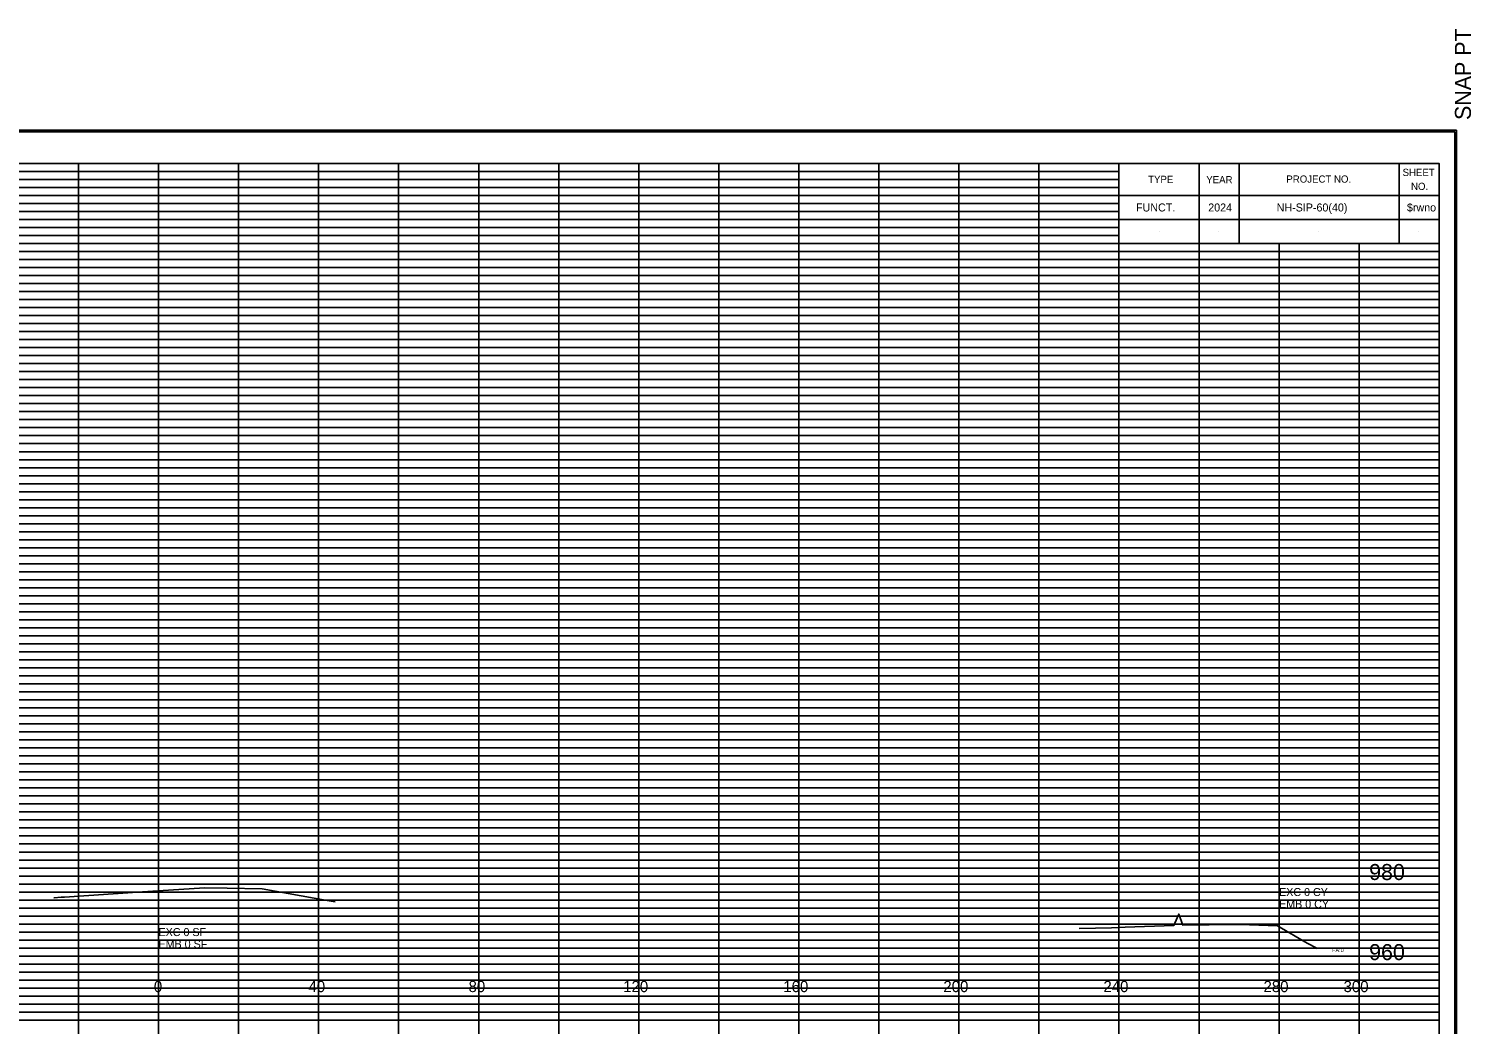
# Model space of a CAD drawing. Extents: x 2313580 to 2322968, y 282099 to 303247.
# Drawn here: x 2321124.9 to 2321485.3, y 287792.7 to 288041.3 of the extents above; entities that cross this region are included whole.
import ezdxf

# ---------------------------------------------------------------- set-up
doc = ezdxf.new("R2010")
doc.units = 0
for name, color, linetype in [('DESIGN - EARTHWORK - Excavation Limit Lines', 7, 'Continuous'), ('DESIGN - SCRATCH - User 1', 7, 'Continuous'), ('DESIGN - SHEET - Corner Text', 7, 'Continuous'), ('DESIGN - SHEET - Light Grid', 7, 'Continuous'), ('DESIGN - SHEET - Linework', 7, 'Continuous'), ('DESIGN - SHEET - Plot Shape', 7, 'Continuous'), ('DESIGN - TYPICAL - Text', 7, 'Continuous'), ('Prop_ CL text', 7, 'Continuous'), ('SURVEY - GROUND - Top of Ground', 7, 'Continuous')]:
    doc.layers.add(name, color=color, linetype=linetype)

msp = doc.modelspace()

# ---------------------------------------------------------------- linework, layer by layer
at = {"layer": 'DESIGN - SCRATCH - User 1'}
for p, q in [((2321407.28, 287996.67), (2321407.28, 287996.67)), ((2321422.08, 287996.67), (2321422.08, 287996.67)), ((2321447.08, 287996.67), (2321447.08, 287996.67)), ((2321472.08, 287996.67), (2321472.08, 287996.67)), ((2321407.28, 287990.67), (2321407.28, 287990.67)), ((2321422.08, 287990.67), (2321422.08, 287990.67)), ((2321447.08, 287990.67), (2321447.08, 287990.67)), ((2321472.08, 287990.67), (2321472.08, 287990.67))]:
    msp.add_line(p, q, dxfattribs=at)
at = {"layer": 'DESIGN - SHEET - Light Grid'}
for p, q in [((2320997.28, 288005.67), (2321157.28, 288005.67)), ((2320997.28, 288003.67), (2321157.28, 288003.67)), ((2321157.28, 288005.67), (2321317.28, 288005.67)), ((2321157.28, 288003.67), (2321317.28, 288003.67)), ((2321317.28, 288005.67), (2321397.28, 288005.67)), ((2321317.28, 288003.67), (2321397.28, 288003.67)), ((2320997.28, 288001.67), (2321157.28, 288001.67)), ((2320997.28, 287999.67), (2321157.28, 287999.67)), ((2321157.28, 288001.67), (2321317.28, 288001.67)), ((2321157.28, 287999.67), (2321317.28, 287999.67)), ((2321317.28, 288001.67), (2321397.28, 288001.67)), ((2321317.28, 287999.67), (2321397.28, 287999.67)), ((2320997.28, 287997.67), (2321157.28, 287997.67)), ((2320997.28, 287995.67), (2321157.28, 287995.67)), ((2321157.28, 287997.67), (2321317.28, 287997.67)), ((2321157.28, 287995.67), (2321317.28, 287995.67)), ((2321317.28, 287997.67), (2321397.28, 287997.67)), ((2321317.28, 287995.67), (2321397.28, 287995.67)), ((2320997.28, 287993.67), (2321157.28, 287993.67)), ((2320997.28, 287991.67), (2321157.28, 287991.67)), ((2321157.28, 287993.67), (2321317.28, 287993.67)), ((2321157.28, 287991.67), (2321317.28, 287991.67)), ((2321317.28, 287993.67), (2321397.28, 287993.67)), ((2321317.28, 287991.67), (2321397.28, 287991.67)), ((2320997.28, 287989.67), (2321157.28, 287989.67)), ((2321157.28, 287989.67), (2321317.28, 287989.67)), ((2321317.28, 287989.67), (2321397.28, 287989.67)), ((2320997.28, 287985.67), (2321157.28, 287985.67)), ((2321157.28, 287985.67), (2321317.28, 287985.67)), ((2321317.28, 287985.67), (2321477.28, 287985.67)), ((2320997.28, 287983.67), (2321157.28, 287983.67)), ((2320997.28, 287981.67), (2321157.28, 287981.67)), ((2321157.28, 287983.67), (2321317.28, 287983.67)), ((2321157.28, 287981.67), (2321317.28, 287981.67)), ((2321317.28, 287983.67), (2321477.28, 287983.67)), ((2321317.28, 287981.67), (2321477.28, 287981.67)), ((2320997.28, 287979.67), (2321157.28, 287979.67)), ((2320997.28, 287977.67), (2321157.28, 287977.67)), ((2321157.28, 287979.67), (2321317.28, 287979.67)), ((2321157.28, 287977.67), (2321317.28, 287977.67)), ((2321317.28, 287979.67), (2321477.28, 287979.67)), ((2321317.28, 287977.67), (2321477.28, 287977.67)), ((2320997.28, 287975.67), (2321157.28, 287975.67)), ((2320997.28, 287973.67), (2321157.28, 287973.67)), ((2321157.28, 287975.67), (2321317.28, 287975.67)), ((2321157.28, 287973.67), (2321317.28, 287973.67)), ((2321317.28, 287975.67), (2321477.28, 287975.67)), ((2321317.28, 287973.67), (2321477.28, 287973.67)), ((2320997.28, 287971.67), (2321157.28, 287971.67)), ((2321157.28, 287971.67), (2321317.28, 287971.67)), ((2321317.28, 287971.67), (2321477.28, 287971.67)), ((2320997.28, 287969.67), (2321157.28, 287969.67)), ((2321157.28, 287969.67), (2321317.28, 287969.67)), ((2321317.28, 287969.67), (2321477.28, 287969.67)), ((2320997.28, 287965.67), (2321157.28, 287965.67)), ((2320997.28, 287963.67), (2321157.28, 287963.67)), ((2321157.28, 287965.67), (2321317.28, 287965.67)), ((2321157.28, 287963.67), (2321317.28, 287963.67)), ((2321317.28, 287965.67), (2321477.28, 287965.67)), ((2321317.28, 287963.67), (2321477.28, 287963.67)), ((2320997.28, 287961.67), (2321157.28, 287961.67)), ((2320997.28, 287959.67), (2321157.28, 287959.67)), ((2321157.28, 287961.67), (2321317.28, 287961.67)), ((2321157.28, 287959.67), (2321317.28, 287959.67)), ((2321317.28, 287961.67), (2321477.28, 287961.67)), ((2321317.28, 287959.67), (2321477.28, 287959.67)), ((2320997.28, 287957.67), (2321157.28, 287957.67)), ((2320997.28, 287955.67), (2321157.28, 287955.67)), ((2321157.28, 287957.67), (2321317.28, 287957.67)), ((2321157.28, 287955.67), (2321317.28, 287955.67)), ((2321317.28, 287957.67), (2321477.28, 287957.67)), ((2321317.28, 287955.67), (2321477.28, 287955.67)), ((2320997.28, 287953.67), (2321157.28, 287953.67)), ((2321157.28, 287953.67), (2321317.28, 287953.67)), ((2321317.28, 287953.67), (2321477.28, 287953.67)), ((2320997.28, 287951.67), (2321157.28, 287951.67)), ((2320997.28, 287949.67), (2321157.28, 287949.67)), ((2321157.28, 287951.67), (2321317.28, 287951.67)), ((2321157.28, 287949.67), (2321317.28, 287949.67)), ((2321317.28, 287951.67), (2321477.28, 287951.67)), ((2321317.28, 287949.67), (2321477.28, 287949.67)), ((2320997.28, 287945.67), (2321157.28, 287945.67)), ((2321157.28, 287945.67), (2321317.28, 287945.67)), ((2321317.28, 287945.67), (2321477.28, 287945.67)), ((2320997.28, 287943.67), (2321157.28, 287943.67)), ((2320997.28, 287941.67), (2321157.28, 287941.67)), ((2321157.28, 287943.67), (2321317.28, 287943.67)), ((2321157.28, 287941.67), (2321317.28, 287941.67)), ((2321317.28, 287943.67), (2321477.28, 287943.67)), ((2321317.28, 287941.67), (2321477.28, 287941.67)), ((2320997.28, 287939.67), (2321157.28, 287939.67)), ((2320997.28, 287937.67), (2321157.28, 287937.67)), ((2321157.28, 287939.67), (2321317.28, 287939.67)), ((2321157.28, 287937.67), (2321317.28, 287937.67)), ((2321317.28, 287939.67), (2321477.28, 287939.67)), ((2321317.28, 287937.67), (2321477.28, 287937.67)), ((2320997.28, 287935.67), (2321157.28, 287935.67)), ((2321157.28, 287935.67), (2321317.28, 287935.67)), ((2321317.28, 287935.67), (2321477.28, 287935.67)), ((2320997.28, 287933.67), (2321157.28, 287933.67)), ((2320997.28, 287931.67), (2321157.28, 287931.67)), ((2321157.28, 287933.67), (2321317.28, 287933.67)), ((2321157.28, 287931.67), (2321317.28, 287931.67)), ((2321317.28, 287933.67), (2321477.28, 287933.67)), ((2321317.28, 287931.67), (2321477.28, 287931.67)), ((2320997.28, 287929.67), (2321157.28, 287929.67)), ((2321157.28, 287929.67), (2321317.28, 287929.67)), ((2321317.28, 287929.67), (2321477.28, 287929.67)), ((2320997.28, 287925.67), (2321157.28, 287925.67)), ((2320997.28, 287923.67), (2321157.28, 287923.67)), ((2321157.28, 287925.67), (2321317.28, 287925.67)), ((2321157.28, 287923.67), (2321317.28, 287923.67)), ((2321317.28, 287925.67), (2321477.28, 287925.67)), ((2321317.28, 287923.67), (2321477.28, 287923.67)), ((2320997.28, 287921.67), (2321157.28, 287921.67)), ((2320997.28, 287919.67), (2321157.28, 287919.67)), ((2321157.28, 287921.67), (2321317.28, 287921.67)), ((2321157.28, 287919.67), (2321317.28, 287919.67)), ((2321317.28, 287921.67), (2321477.28, 287921.67)), ((2321317.28, 287919.67), (2321477.28, 287919.67)), ((2320997.28, 287917.67), (2321157.28, 287917.67)), ((2321157.28, 287917.67), (2321317.28, 287917.67)), ((2321317.28, 287917.67), (2321477.28, 287917.67)), ((2320997.28, 287915.67), (2321157.28, 287915.67)), ((2320997.28, 287913.67), (2321157.28, 287913.67)), ((2321157.28, 287915.67), (2321317.28, 287915.67)), ((2321157.28, 287913.67), (2321317.28, 287913.67)), ((2321317.28, 287915.67), (2321477.28, 287915.67)), ((2321317.28, 287913.67), (2321477.28, 287913.67)), ((2320997.28, 287911.67), (2321157.28, 287911.67)), ((2320997.28, 287909.67), (2321157.28, 287909.67)), ((2321157.28, 287911.67), (2321317.28, 287911.67)), ((2321157.28, 287909.67), (2321317.28, 287909.67)), ((2321317.28, 287911.67), (2321477.28, 287911.67)), ((2321317.28, 287909.67), (2321477.28, 287909.67)), ((2320997.28, 287905.67), (2321157.28, 287905.67)), ((2321157.28, 287905.67), (2321317.28, 287905.67)), ((2321317.28, 287905.67), (2321477.28, 287905.67)), ((2320997.28, 287903.67), (2321157.28, 287903.67)), ((2320997.28, 287901.67), (2321157.28, 287901.67)), ((2321157.28, 287903.67), (2321317.28, 287903.67)), ((2321157.28, 287901.67), (2321317.28, 287901.67)), ((2321317.28, 287903.67), (2321477.28, 287903.67)), ((2321317.28, 287901.67), (2321477.28, 287901.67)), ((2320997.28, 287899.67), (2321157.28, 287899.67)), ((2321157.28, 287899.67), (2321317.28, 287899.67)), ((2321317.28, 287899.67), (2321477.28, 287899.67)), ((2320997.28, 287897.67), (2321157.28, 287897.67)), ((2320997.28, 287895.67), (2321157.28, 287895.67)), ((2321157.28, 287897.67), (2321317.28, 287897.67)), ((2321157.28, 287895.67), (2321317.28, 287895.67)), ((2321317.28, 287897.67), (2321477.28, 287897.67)), ((2321317.28, 287895.67), (2321477.28, 287895.67)), ((2320997.28, 287893.67), (2321157.28, 287893.67)), ((2320997.28, 287891.67), (2321157.28, 287891.67)), ((2321157.28, 287893.67), (2321317.28, 287893.67)), ((2321157.28, 287891.67), (2321317.28, 287891.67)), ((2321317.28, 287893.67), (2321477.28, 287893.67)), ((2321317.28, 287891.67), (2321477.28, 287891.67)), ((2320997.28, 287889.67), (2321157.28, 287889.67)), ((2321157.28, 287889.67), (2321317.28, 287889.67)), ((2321317.28, 287889.67), (2321477.28, 287889.67)), ((2320997.28, 287885.67), (2321157.28, 287885.67)), ((2320997.28, 287883.67), (2321157.28, 287883.67)), ((2321157.28, 287885.67), (2321317.28, 287885.67)), ((2321157.28, 287883.67), (2321317.28, 287883.67)), ((2321317.28, 287885.67), (2321477.28, 287885.67)), ((2321317.28, 287883.67), (2321477.28, 287883.67)), ((2320997.28, 287881.67), (2321157.28, 287881.67)), ((2321157.28, 287881.67), (2321317.28, 287881.67)), ((2321317.28, 287881.67), (2321477.28, 287881.67)), ((2320997.28, 287879.67), (2321157.28, 287879.67)), ((2320997.28, 287877.67), (2321157.28, 287877.67)), ((2321157.28, 287879.67), (2321317.28, 287879.67)), ((2321157.28, 287877.67), (2321317.28, 287877.67)), ((2321317.28, 287879.67), (2321477.28, 287879.67)), ((2321317.28, 287877.67), (2321477.28, 287877.67)), ((2320997.28, 287875.67), (2321157.28, 287875.67)), ((2320997.28, 287873.67), (2321157.28, 287873.67)), ((2321157.28, 287875.67), (2321317.28, 287875.67)), ((2321157.28, 287873.67), (2321317.28, 287873.67)), ((2321317.28, 287875.67), (2321477.28, 287875.67)), ((2321317.28, 287873.67), (2321477.28, 287873.67)), ((2320997.28, 287871.67), (2321157.28, 287871.67)), ((2320997.28, 287869.67), (2321157.28, 287869.67)), ((2321157.28, 287871.67), (2321317.28, 287871.67)), ((2321157.28, 287869.67), (2321317.28, 287869.67)), ((2321317.28, 287871.67), (2321477.28, 287871.67)), ((2321317.28, 287869.67), (2321477.28, 287869.67)), ((2320997.28, 287865.67), (2321157.28, 287865.67)), ((2321157.28, 287865.67), (2321317.28, 287865.67)), ((2321317.28, 287865.67), (2321477.28, 287865.67)), ((2320997.28, 287863.67), (2321157.28, 287863.67)), ((2321157.28, 287863.67), (2321317.28, 287863.67)), ((2321317.28, 287863.67), (2321477.28, 287863.67)), ((2320997.28, 287861.67), (2321157.28, 287861.67)), ((2320997.28, 287859.67), (2321157.28, 287859.67)), ((2321157.28, 287861.67), (2321317.28, 287861.67)), ((2321157.28, 287859.67), (2321317.28, 287859.67)), ((2321317.28, 287861.67), (2321477.28, 287861.67)), ((2321317.28, 287859.67), (2321477.28, 287859.67)), ((2320997.28, 287857.67), (2321157.28, 287857.67)), ((2320997.28, 287855.67), (2321157.28, 287855.67)), ((2321157.28, 287857.67), (2321317.28, 287857.67)), ((2321157.28, 287855.67), (2321317.28, 287855.67)), ((2321317.28, 287857.67), (2321477.28, 287857.67)), ((2321317.28, 287855.67), (2321477.28, 287855.67)), ((2320997.28, 287853.67), (2321157.28, 287853.67)), ((2320997.28, 287851.67), (2321157.28, 287851.67)), ((2321157.28, 287853.67), (2321317.28, 287853.67)), ((2321157.28, 287851.67), (2321317.28, 287851.67)), ((2321317.28, 287853.67), (2321477.28, 287853.67)), ((2321317.28, 287851.67), (2321477.28, 287851.67)), ((2320997.28, 287849.67), (2321157.28, 287849.67)), ((2321157.28, 287849.67), (2321317.28, 287849.67)), ((2321317.28, 287849.67), (2321477.28, 287849.67)), ((2320997.28, 287845.67), (2321157.28, 287845.67)), ((2321157.28, 287845.67), (2321317.28, 287845.67)), ((2321317.28, 287845.67), (2321477.28, 287845.67)), ((2320997.28, 287843.67), (2321157.28, 287843.67)), ((2320997.28, 287841.67), (2321157.28, 287841.67)), ((2321157.28, 287843.67), (2321317.28, 287843.67)), ((2321157.28, 287841.67), (2321317.28, 287841.67)), ((2321317.28, 287843.67), (2321477.28, 287843.67)), ((2321317.28, 287841.67), (2321477.28, 287841.67)), ((2320997.28, 287839.67), (2321157.28, 287839.67)), ((2320997.28, 287837.67), (2321157.28, 287837.67)), ((2321157.28, 287839.67), (2321317.28, 287839.67)), ((2321157.28, 287837.67), (2321317.28, 287837.67)), ((2321317.28, 287839.67), (2321477.28, 287839.67)), ((2321317.28, 287837.67), (2321477.28, 287837.67)), ((2320997.28, 287835.67), (2321157.28, 287835.67)), ((2320997.28, 287833.67), (2321157.28, 287833.67)), ((2321157.28, 287835.67), (2321317.28, 287835.67)), ((2321157.28, 287833.67), (2321317.28, 287833.67)), ((2321317.28, 287835.67), (2321477.28, 287835.67)), ((2321317.28, 287833.67), (2321477.28, 287833.67)), ((2320997.28, 287831.67), (2321157.28, 287831.67)), ((2320997.28, 287829.67), (2321157.28, 287829.67)), ((2321157.28, 287831.67), (2321317.28, 287831.67)), ((2321157.28, 287829.67), (2321317.28, 287829.67)), ((2321317.28, 287831.67), (2321477.28, 287831.67)), ((2321317.28, 287829.67), (2321477.28, 287829.67)), ((2320997.28, 287825.67), (2321157.28, 287825.67)), ((2320997.28, 287823.67), (2321157.28, 287823.67)), ((2321157.28, 287825.67), (2321317.28, 287825.67)), ((2321157.28, 287823.67), (2321317.28, 287823.67)), ((2321317.28, 287825.67), (2321477.28, 287825.67)), ((2321317.28, 287823.67), (2321477.28, 287823.67)), ((2320997.28, 287821.67), (2321157.28, 287821.67)), ((2320997.28, 287819.67), (2321157.28, 287819.67)), ((2321157.28, 287821.67), (2321317.28, 287821.67)), ((2321157.28, 287819.67), (2321317.28, 287819.67)), ((2321317.28, 287821.67), (2321477.28, 287821.67)), ((2321317.28, 287819.67), (2321477.28, 287819.67)), ((2320997.28, 287817.67), (2321157.28, 287817.67)), ((2320997.28, 287815.67), (2321157.28, 287815.67)), ((2321157.28, 287817.67), (2321317.28, 287817.67)), ((2321157.28, 287815.67), (2321317.28, 287815.67)), ((2321317.28, 287817.67), (2321477.28, 287817.67)), ((2321317.28, 287815.67), (2321477.28, 287815.67)), ((2320997.28, 287813.67), (2321157.28, 287813.67)), ((2320997.28, 287811.67), (2321157.28, 287811.67)), ((2321157.28, 287813.67), (2321317.28, 287813.67)), ((2321157.28, 287811.67), (2321317.28, 287811.67)), ((2321317.28, 287813.67), (2321477.28, 287813.67)), ((2321317.28, 287811.67), (2321477.28, 287811.67)), ((2320997.28, 287809.67), (2321157.28, 287809.67)), ((2321157.28, 287809.67), (2321317.28, 287809.67)), ((2321317.28, 287809.67), (2321477.28, 287809.67)), ((2320997.28, 287805.67), (2321157.28, 287805.67)), ((2321157.28, 287805.67), (2321317.28, 287805.67)), ((2321317.28, 287805.67), (2321477.28, 287805.67)), ((2320997.28, 287803.67), (2321157.28, 287803.67)), ((2320997.28, 287801.67), (2321157.28, 287801.67)), ((2321157.28, 287803.67), (2321317.28, 287803.67)), ((2321157.28, 287801.67), (2321317.28, 287801.67)), ((2321317.28, 287803.67), (2321477.28, 287803.67)), ((2321317.28, 287801.67), (2321477.28, 287801.67)), ((2320997.28, 287799.67), (2321157.28, 287799.67)), ((2320997.28, 287797.67), (2321157.28, 287797.67)), ((2321157.28, 287799.67), (2321317.28, 287799.67)), ((2321157.28, 287797.67), (2321317.28, 287797.67)), ((2321317.28, 287799.67), (2321477.28, 287799.67)), ((2321317.28, 287797.67), (2321477.28, 287797.67)), ((2320997.28, 287795.67), (2321157.28, 287795.67)), ((2320997.28, 287793.67), (2321157.28, 287793.67)), ((2321157.28, 287795.67), (2321317.28, 287795.67)), ((2321157.28, 287793.67), (2321317.28, 287793.67)), ((2321317.28, 287795.67), (2321477.28, 287795.67)), ((2321317.28, 287793.67), (2321477.28, 287793.67))]:
    msp.add_line(p, q, dxfattribs=at)
at = {"layer": 'DESIGN - SHEET - Linework'}
for p, q in [((2320800.82, 288015.95), (2321481.62, 288015.95)), ((2321481.62, 288015.95), (2321481.62, 287579.39)), ((2321137.28, 287587.67), (2321137.28, 288007.67)), ((2321157.28, 287587.67), (2321157.28, 288007.67)), ((2321177.28, 287587.67), (2321177.28, 288007.67)), ((2321197.28, 287587.67), (2321197.28, 288007.67)), ((2321217.28, 287587.67), (2321217.28, 288007.67)), ((2321237.28, 287587.67), (2321237.28, 288007.67)), ((2321257.28, 287587.67), (2321257.28, 288007.67)), ((2321277.28, 287587.67), (2321277.28, 288007.67)), ((2321297.28, 287587.67), (2321297.28, 288007.67)), ((2321317.28, 287587.67), (2321317.28, 288007.67)), ((2321337.28, 287587.67), (2321337.28, 288007.67)), ((2321357.28, 287587.67), (2321357.28, 288007.67)), ((2321377.28, 287587.67), (2321377.28, 288007.67)), ((2320837.28, 287987.67), (2321397.28, 287987.67)), ((2321397.28, 287587.67), (2321397.28, 287987.67)), ((2321417.28, 287587.67), (2321417.28, 287987.67)), ((2321437.28, 287587.67), (2321437.28, 287987.67)), ((2321457.28, 287587.67), (2321457.28, 287987.67)), ((2320837.28, 287967.67), (2321477.28, 287967.67)), ((2320837.28, 287947.67), (2321477.28, 287947.67)), ((2320837.28, 287927.67), (2321477.28, 287927.67)), ((2320837.28, 287907.67), (2321477.28, 287907.67)), ((2320837.28, 287887.67), (2321477.28, 287887.67)), ((2320837.28, 287867.67), (2321477.28, 287867.67)), ((2320837.28, 287847.67), (2321477.28, 287847.67)), ((2320837.28, 287827.67), (2321477.28, 287827.67)), ((2320837.28, 287807.67), (2321477.28, 287807.67))]:
    msp.add_line(p, q, dxfattribs=at)
for points in [[(2320837.28, 288007.67), (2320837.28, 287587.67), (2321477.28, 287587.67), (2321477.28, 288007.67), (2320837.28, 288007.67)], [(2321397.28, 288007.67), (2321397.28, 287987.67), (2321477.28, 287987.67), (2321477.28, 288007.67), (2321467.28, 288007.67), (2321467.28, 287987.67), (2321427.28, 287987.67), (2321427.28, 288007.67), (2321417.28, 288007.67), (2321417.28, 287987.67), (2321477.28, 287987.67), (2321397.28, 287987.67), (2321397.28, 287993.67), (2321477.28, 287993.67), (2321477.28, 287999.67), (2321397.28, 287999.67)]]:
    msp.add_lwpolyline(points, dxfattribs=at)
at = {"layer": 'DESIGN - SHEET - Plot Shape'}
for points in [[(2320801.22, 288015.55), (2321481.22, 288015.55), (2321481.22, 287579.79), (2320801.22, 287579.79)], [(2320820.28, 288007.67), (2321477.28, 288007.67), (2321477.28, 287582.67), (2320820.28, 287582.67)]]:
    msp.add_lwpolyline(points, close=True, dxfattribs=at)
at = {"layer": 'SURVEY - GROUND - Top of Ground'}
for points in [[(2321131.11, 287824.21), (2321131.2, 287824.22), (2321132.97, 287824.37), (2321133.75, 287824.43), (2321152, 287825.63), (2321168.8, 287826.73), (2321174.42, 287826.64), (2321183.17, 287826.47), (2321199.4, 287823.57), (2321201.44, 287823.25)], [(2321387.3, 287816.54), (2321391.43, 287816.65), (2321395.43, 287816.76), (2321398.83, 287816.89), (2321411.01, 287817.35), (2321411.82, 287819.2), (2321412.21, 287820.16), (2321412.55, 287819.22), (2321413.19, 287817.42), (2321426.41, 287817.55), (2321428.45, 287817.56), (2321429.85, 287817.5), (2321436.89, 287817.21), (2321444.31, 287812.9), (2321446.72, 287811.64), (2321446.82, 287811.49)]]:
    msp.add_lwpolyline(points, dxfattribs=at)

# ---------------------------------------------------------------- texts
at = {"layer": 'DESIGN - EARTHWORK - Excavation Limit Lines'}
for s, p in [('EXC 0 CY', (2321437.28, 287824.67)), ('EMB 0 CY', (2321437.28, 287821.67)), ('EXC 0 SF', (2321157.28, 287814.67)), ('EMB 0 SF', (2321157.28, 287811.67))]:
    msp.add_text(s, height=2, dxfattribs=at).set_placement(p)
at = {"layer": 'DESIGN - SHEET - Corner Text'}
for s, height, rotation, p in [('  SNAP PT', 4, 90, (2321485.22, 288015.55)), ('SHEET', 1.8, 360, (2321468.14, 288004.53)), ('TYPE', 1.8, 360, (2321404.56, 288002.79)), ('YEAR', 1.8, 360, (2321419.09, 288002.71)), ('PROJECT NO.', 1.8, 360, (2321439.1, 288002.87)), ('NO.', 1.8, 360, (2321470.25, 288001.05)), ('  FUNCT.   ', 2, 360, (2321400.05, 287995.67)), ('2024', 2, 360, (2321419.58, 287995.67)), ('    NH-SIP-60(40)   ', 2, 360, (2321433.7, 287995.67)), ('$rwno', 2, 360, (2321469.23, 287995.67))]:
    msp.add_text(s, height=height, rotation=rotation, dxfattribs=at).set_placement(p)
at = {"layer": 'DESIGN - TYPICAL - Text'}
for s, height, p in [('980', 4, (2321459.78, 287828.67)), ('960', 4, (2321459.78, 287808.67)), ('0', 2.8, (2321156.12, 287800.67)), ('40', 2.8, (2321194.75, 287800.67)), ('80', 2.8, (2321234.75, 287800.67)), ('120', 2.8, (2321273.39, 287800.67)), ('160', 2.8, (2321313.39, 287800.67)), ('200', 2.8, (2321353.39, 287800.67)), ('240', 2.8, (2321393.39, 287800.67)), ('280', 2.8, (2321433.39, 287800.67)), ('300', 2.8, (2321453.39, 287800.67))]:
    msp.add_text(s, height=height, dxfattribs=at).set_placement(p)
at = {"layer": 'Prop_ CL text'}
msp.add_text('FA:0', height=1, dxfattribs=at).set_placement((2321450.52, 287810.67))

doc.saveas('drawing.dxf')
